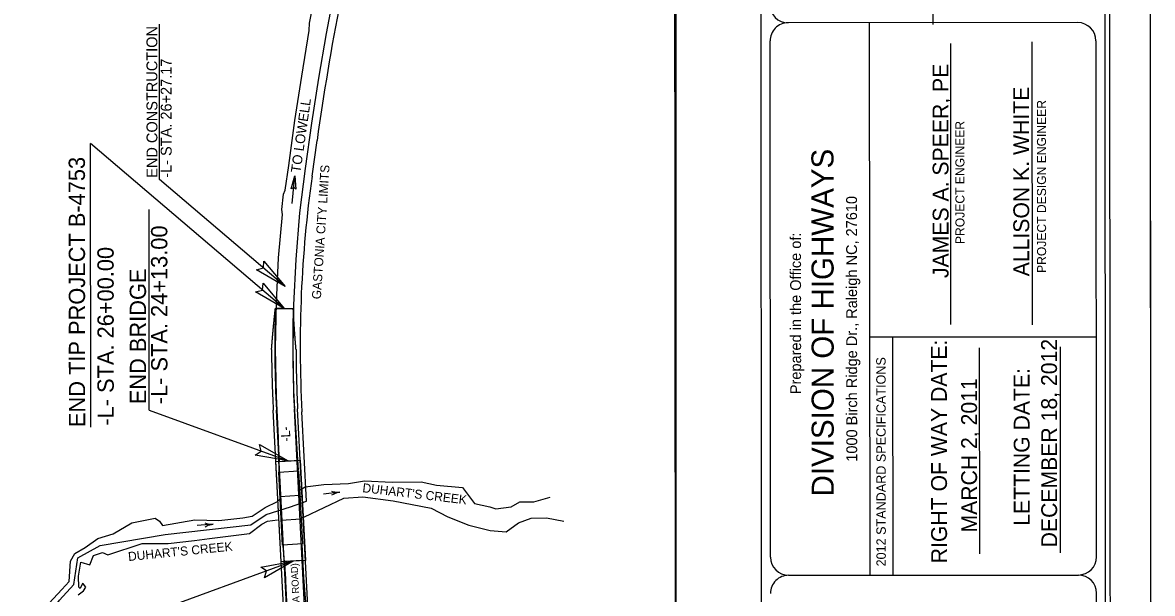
# Model space of a CAD drawing. Extents: x 1372027 to 1374286, y 553832 to 556743.
# Drawn here: x 1373560 to 1374184, y 554785 to 555100 of the extents above; entities that cross this region are included whole.
import ezdxf

# ---------------------------------------------------------------- set-up
doc = ezdxf.new("R2010")
doc.units = 0
for name, color, linetype in [('Default', 7, 'Continuous'), ('Prop Approach Slab', 7, 'Continuous'), ('Prop Approach Slab Hatching', 7, 'Continuous'), ('Prop Dimension', 7, 'Continuous'), ('Prop Dimension Text', 7, 'Continuous'), ('Prop EOT', 7, 'Continuous'), ('Prop Horizontal Alignment Curve and Spiral Data', 7, 'Continuous'), ('Prop Horizontal Alignment Station Label', 7, 'Continuous'), ('Prop North Arrow for Plan Sheets CELL', 7, 'Continuous'), ('Prop North Arrow NAD83 for Plan Sheets CELL', 7, 'Continuous'), ('Prop Paved Shoulder', 7, 'Continuous'), ('Prop Roadway Bridge', 7, 'Continuous'), ('Prop Shade Light', 7, 'Continuous'), ('Prop Structure Anchor Unit CELL', 7, 'Continuous'), ('Prop Terminator CELL', 7, 'Continuous'), ('Sheet Clip Boundary CELL', 7, 'Continuous'), ('Sheet Layout Plan Border', 7, 'Continuous'), ('Sheet Plan Layout CELL', 7, 'Continuous'), ('Sheet Plot Border Inside CELL', 7, 'Continuous')]:
    doc.layers.add(name, color=color, linetype=linetype)

msp = doc.modelspace()

# ---------------------------------------------------------------- linework, layer by layer
at = {"layer": 'Default'}
msp.add_line((1373708.71, 554999.98), (1373710.28, 555015.32), dxfattribs=at)
at = {"layer": 'Prop Approach Slab'}
msp.add_lwpolyline([(1374161.39, 553845.95), (1374159.91, 555512.45), (1373104.81, 555511.51), (1373106.29, 553845.01)], close=True, dxfattribs=at)
at = {"layer": 'Prop Approach Slab Hatching'}
msp.add_lwpolyline([(1373082.36, 555515.99), (1373083.86, 553831.99), (1374183.84, 553832.97), (1374182.35, 555516.97)], close=True, dxfattribs=at)
at = {"layer": 'Prop Dimension'}
for p, q in [((1373635.55, 555013.27), (1373635.48, 555099.03)), ((1373704.44, 554942), (1373597.42, 555033.13)), ((1373597.56, 554876.52), (1373597.42, 555033.13)), ((1373704.91, 554954.22), (1373635.55, 555013.27)), ((1373629.87, 554885.96), (1373629.77, 554996.81)), ((1373629.87, 554885.96), (1373706.54, 554857.91)), ((1373709.4, 554802.64), (1373629.97, 554773.41))]:
    msp.add_line(p, q, dxfattribs=at)
at = {"layer": 'Prop Dimension Text'}
for p, q in [((1373699.8, 554857.56), (1373713.28, 554858.26)), ((1373713.28, 554858.26), (1373716.14, 554802.98)), ((1373702.65, 554802.29), (1373699.8, 554857.56)), ((1373716.14, 554802.98), (1373702.65, 554802.29))]:
    msp.add_line(p, q, dxfattribs=at)
msp.add_lwpolyline([(1373448.16, 554513.79), (1373448.16, 555188.2), (1373920.65, 555188.2), (1373920.65, 554513.79)], close=True, dxfattribs=at)
at = {"layer": 'Prop EOT'}
for p, q in [((1373699.5, 554942.15), (1373709.39, 554941.86)), ((1373707.12, 554750.7), (1373700.13, 554886)), ((1373715.64, 554777.72), (1373710.02, 554886.51))]:
    msp.add_line(p, q, dxfattribs=at)
for radius in [695.7, 685.8]:
    msp.add_arc((1374394.9, 554921.9), radius, 178.33248, 182.95848, dxfattribs=at)
at = {"layer": 'Prop Horizontal Alignment Curve and Spiral Data'}
for p, q in [((1373702.12, 554838.27), (1373712.9, 554838.99)), ((1373713.51, 554825.81), (1373702.8, 554825.03))]:
    msp.add_line(p, q, dxfattribs=at)
msp.add_lwpolyline([(1373714.41, 554812.07), (1373703.39, 554811.4), (1373701.45, 554851.65), (1373712.34, 554852.38), (1373714.41, 554812.07)], dxfattribs=at)
at = {"layer": 'Prop North Arrow for Plan Sheets CELL'}
msp.add_lwpolyline([(1373708.29, 555008.2), (1373710.28, 555015.32), (1373710.82, 555007.9), (1373709.63, 555008.96)], close=True, dxfattribs=at)
at = {"layer": 'Prop Paved Shoulder'}
for p, q in [((1373706.49, 554728.14), (1373698.33, 554885.9)), ((1373717.94, 554768.14), (1373711.81, 554886.6))]:
    msp.add_line(p, q, dxfattribs=at)
for radius in [697.5, 684]:
    msp.add_arc((1374394.9, 554921.9), radius, 180.19879, 182.95848, dxfattribs=at)
for points in [[(1373697.41, 554919.48), (1373697.43, 554919.79), (1373697.45, 554920.1), (1373697.48, 554920.41), (1373697.5, 554920.71), (1373697.52, 554921.02), (1373697.55, 554921.33), (1373697.57, 554921.63), (1373697.6, 554921.94), (1373697.62, 554922.25), (1373697.65, 554922.55), (1373697.67, 554922.86), (1373697.7, 554923.17), (1373697.72, 554923.47), (1373697.75, 554923.78), (1373697.77, 554924.09), (1373697.8, 554924.39), (1373697.82, 554924.7), (1373697.85, 554925.01), (1373697.87, 554925.32), (1373697.9, 554925.62), (1373697.92, 554925.93), (1373697.95, 554926.24), (1373697.98, 554926.54), (1373698, 554926.85), (1373698.03, 554927.15), (1373698.06, 554927.46), (1373698.08, 554927.77), (1373698.11, 554928.07), (1373698.14, 554928.38), (1373698.16, 554928.69), (1373698.19, 554928.99), (1373698.22, 554929.3), (1373698.25, 554929.61), (1373698.28, 554929.91), (1373698.3, 554930.22), (1373698.33, 554930.53), (1373698.36, 554930.83), (1373698.39, 554931.14), (1373698.42, 554931.44), (1373698.44, 554931.75), (1373698.47, 554932.06), (1373698.5, 554932.36), (1373698.53, 554932.67), (1373698.56, 554932.98), (1373698.59, 554933.28), (1373698.62, 554933.59), (1373698.65, 554933.89), (1373698.68, 554934.2), (1373698.71, 554934.51), (1373698.74, 554934.81), (1373698.77, 554935.12), (1373698.8, 554935.42), (1373698.83, 554935.73), (1373698.86, 554936.04), (1373698.89, 554936.34), (1373698.92, 554936.65), (1373698.95, 554936.95), (1373698.98, 554937.26), (1373699.01, 554937.56), (1373699.04, 554937.87), (1373699.08, 554938.18), (1373699.11, 554938.48), (1373699.14, 554938.79), (1373699.17, 554939.09), (1373699.2, 554939.4), (1373699.24, 554939.7), (1373699.27, 554940.01), (1373699.3, 554940.32), (1373699.33, 554940.62), (1373699.36, 554940.93), (1373699.4, 554941.23), (1373699.43, 554941.54), (1373699.5, 554942.15)], [(1373710.91, 554919.53), (1373710.88, 554919.83), (1373710.86, 554920.13), (1373710.83, 554920.43), (1373710.81, 554920.73), (1373710.78, 554921.04), (1373710.76, 554921.34), (1373710.73, 554921.64), (1373710.71, 554921.94), (1373710.68, 554922.24), (1373710.66, 554922.54), (1373710.64, 554922.84), (1373710.61, 554923.14), (1373710.59, 554923.45), (1373710.56, 554923.75), (1373710.54, 554924.05), (1373710.52, 554924.35), (1373710.49, 554924.65), (1373710.47, 554924.95), (1373710.45, 554925.25), (1373710.43, 554925.56), (1373710.4, 554925.86), (1373710.38, 554926.16), (1373710.36, 554926.46), (1373710.34, 554926.76), (1373710.31, 554927.06), (1373710.29, 554927.36), (1373710.27, 554927.67), (1373710.25, 554927.97), (1373710.23, 554928.27), (1373710.2, 554928.57), (1373710.18, 554928.87), (1373710.16, 554929.17), (1373710.14, 554929.48), (1373710.12, 554929.78), (1373710.1, 554930.08), (1373710.08, 554930.38), (1373710.06, 554930.68), (1373710.04, 554930.98), (1373710.02, 554931.29), (1373710, 554931.59), (1373709.98, 554931.89), (1373709.96, 554932.19), (1373709.94, 554932.49), (1373709.92, 554932.8), (1373709.9, 554933.1), (1373709.88, 554933.4), (1373709.86, 554933.7), (1373709.84, 554934), (1373709.82, 554934.3), (1373709.8, 554934.61), (1373709.79, 554934.91), (1373709.77, 554935.21), (1373709.75, 554935.51), (1373709.73, 554935.81), (1373709.71, 554936.12), (1373709.69, 554936.42), (1373709.68, 554936.72), (1373709.66, 554937.02), (1373709.64, 554937.33), (1373709.62, 554937.63), (1373709.61, 554937.93), (1373709.59, 554938.23), (1373709.57, 554938.53), (1373709.55, 554938.84), (1373709.54, 554939.14), (1373709.52, 554939.44), (1373709.5, 554939.74), (1373709.49, 554940.05), (1373709.47, 554940.35), (1373709.46, 554940.65), (1373709.44, 554940.95), (1373709.42, 554941.26), (1373709.39, 554941.86)]]:
    msp.add_spline(points, degree=3, dxfattribs=at)
at = {"layer": 'Prop Roadway Bridge'}
for p, q in [((1373968.64, 554064.77), (1373967.37, 555484.77)), ((1374062.69, 555098.96), (1374062.5, 555319.63)), ((1374142.73, 555099.93), (1373982.73, 555099.79)), ((1374027.48, 555099.83), (1374027.74, 554794.83)), ((1373972.98, 554804.78), (1373972.73, 555089.78)), ((1374117.62, 554933.01), (1374117.48, 555089.26)), ((1374072.62, 554933.32), (1374072.49, 555088.47)), ((1374027.62, 554926.38), (1374152.87, 554926.49)), ((1374040.38, 554926.39), (1374040.49, 554794.84)), ((1374132.83, 554920.87), (1374132.93, 554807.12)), ((1374088.23, 554920.43), (1374088.33, 554806.68)), ((1374040.4, 554888.49), (1374040.4, 554888.49)), ((1374088.29, 554863.53), (1374088.29, 554863.53)), ((1373982.99, 554794.79), (1374142.99, 554794.93))]:
    msp.add_line(p, q, dxfattribs=at)
for points in [[(1374158.7, 554009.94), (1374157.38, 555489.94)], [(1374152.98, 554804.94), (1374152.74, 555089.94)], [(1374153.35, 554404.94), (1374153.01, 554784.94)]]:
    msp.add_lwpolyline(points, dxfattribs=at)
for centre, start, end in [((1373982.66, 555109.79), 180.05095, 270.05095), ((1373982.68, 555089.79), 90.05095, 180.05095), ((1374142.68, 555089.93), 0.05095, 90.05095), ((1373982.93, 554804.79), 180.05095, 270.05095), ((1374142.93, 554804.93), 270.05095, 0.05095), ((1373982.95, 554784.79), 90.05095, 180.05095), ((1374142.95, 554784.93), 0.05095, 90.05095)]:
    msp.add_arc(centre, 10, start, end, dxfattribs=at)
at = {"layer": 'Prop Shade Light'}
msp.add_line((1373700.13, 554886), (1373701.59, 554857.66), dxfattribs=at)
for points in [[(1373709.39, 554941.86), (1373704.44, 554942), (1373699.5, 554942.15)], [(1373701.59, 554857.66), (1373711.48, 554858.17), (1373710.02, 554886.51)]]:
    msp.add_lwpolyline(points, dxfattribs=at)
msp.add_lwpolyline([(1373714.34, 554802.89), (1373704.46, 554802.38), (1373707.12, 554750.7), (1373709.42, 554705.76), (1373714.39, 554706.01), (1373719.33, 554706.27), (1373717.01, 554751.21)], close=True, dxfattribs=at)
for radius in [695.7, 685.8]:
    msp.add_arc((1374394.9, 554921.9), radius, 178.33248, 182.95848, dxfattribs=at)
at = {"layer": 'Prop Structure Anchor Unit CELL'}
msp.add_line((1374183.84, 553832.97), (1374182.35, 555516.97), dxfattribs=at)
at = {"layer": 'Prop Terminator CELL'}
for points in [[(1373719.76, 555015.1), (1373722.54, 555034.92)], [(1373716.77, 554835.64), (1373714.15, 554885.05)], [(1373508.72, 554630.78), (1373513.73, 554667.88), (1373511.28, 554712.53), (1373529.75, 554755.21), (1373574.28, 554772.47), (1373580.36, 554781.04), (1373588.29, 554789.72), (1373590.48, 554804.48), (1373602.72, 554811.26), (1373638.71, 554817.3), (1373685.99, 554822.67), (1373694.48, 554828.39), (1373707.82, 554832.57), (1373716.77, 554835.64)]]:
    msp.add_lwpolyline(points, dxfattribs=at)
for points in [[(1373693.21, 554968.25), (1373704.91, 554954.22), (1373689.05, 554963.52), (1373692.88, 554964.46)], [(1373692.75, 554956.03), (1373704.44, 554942), (1373688.59, 554951.3), (1373692.41, 554952.25)], [(1373690.7, 554867.01), (1373706.54, 554857.91), (1373688.44, 554861.13), (1373691.7, 554863.34)], [(1373691.44, 554799.33), (1373709.4, 554802.64), (1373693.52, 554793.38), (1373694.57, 554797.18)]]:
    msp.add_lwpolyline(points, close=True, dxfattribs=at)
for centre, radius, start, end in [((1375172.7, 554831.81), 1464.32, 165.9137, 172.027), ((1374391.75, 554920.98), 678.55, 172.027, 183.03553)]:
    msp.add_arc(centre, radius, start, end, dxfattribs=at)
at = {"layer": 'Sheet Clip Boundary CELL'}
msp.add_lwpolyline([(1373920.63, 554536.72), (1373920.07, 555166.73), (1373542.74, 555166.39), (1373542.82, 555081.22), (1373447.65, 555081.14), (1373448.5, 554711.84), (1373547.67, 554711.94), (1373547.83, 554537.32)], close=True, dxfattribs=at)
at = {"layer": 'Sheet Layout Plan Border'}
for p, q in [((1373739.98, 554845.53), (1373748.79, 554846.93)), ((1373748.79, 554846.93), (1373763.99, 554846.27)), ((1373763.99, 554846.27), (1373780.03, 554846.41)), ((1373780.03, 554846.41), (1373788.56, 554844.47)), ((1373713.73, 554842.37), (1373716.04, 554843.59)), ((1373714.24, 554839.67), (1373713.73, 554842.37)), ((1373714.28, 554838.3), (1373714.24, 554839.67)), ((1373716.04, 554843.59), (1373726.29, 554844.84)), ((1373735.08, 554840.76), (1373726.17, 554839.56)), ((1373726.29, 554844.84), (1373739.98, 554845.53)), ((1373730.49, 554841.18), (1373731.38, 554840.94)), ((1373730.62, 554840.16), (1373730.62, 554840.16)), ((1373730.76, 554839.14), (1373731.56, 554839.61)), ((1373731.38, 554840.94), (1373732.29, 554840.78)), ((1373731.56, 554839.61), (1373732.4, 554840.01)), ((1373732.29, 554840.78), (1373733.23, 554840.69)), ((1373732.4, 554840.01), (1373733.28, 554840.34)), ((1373733.23, 554840.69), (1373734.17, 554840.67)), ((1373733.28, 554840.34), (1373734.17, 554840.61)), ((1373734.17, 554840.61), (1373735.08, 554840.76)), ((1373734.17, 554840.67), (1373735.08, 554840.76)), ((1373788.56, 554844.47), (1373802.94, 554843.26)), ((1373802.94, 554843.26), (1373809.51, 554834.44)), ((1373693.85, 554832.13), (1373700.73, 554835.46)), ((1373700.73, 554835.46), (1373702.16, 554836.99)), ((1373713.06, 554838.23), (1373714.28, 554838.3)), ((1373715.58, 554827.07), (1373737.26, 554837.38)), ((1373737.26, 554837.38), (1373747.82, 554838.08)), ((1373747.82, 554838.08), (1373764.49, 554835.82)), ((1373764.49, 554835.82), (1373785.51, 554831.85)), ((1373809.51, 554834.44), (1373817.99, 554832.65)), ((1373829.81, 554832.59), (1373834.42, 554835.3)), ((1373834.42, 554835.3), (1373842.23, 554835.35)), ((1373842.23, 554835.35), (1373851.29, 554837.85)), ((1373681.49, 554826.56), (1373686.69, 554827.5)), ((1373686.69, 554827.5), (1373693.85, 554832.13)), ((1373713.66, 554826.7), (1373715.58, 554827.07)), ((1373785.51, 554831.85), (1373794.7, 554826.99)), ((1373794.7, 554826.99), (1373806.43, 554822.44)), ((1373817.99, 554832.65), (1373821.3, 554831.44)), ((1373821.3, 554831.44), (1373829.81, 554832.59)), ((1373609.97, 554817.61), (1373620.3, 554823.73)), ((1373620.3, 554823.73), (1373633.1, 554826.23)), ((1373633.1, 554826.23), (1373635.59, 554824.69)), ((1373635.59, 554824.69), (1373637.18, 554822.21)), ((1373637.18, 554822.21), (1373655.12, 554825.32)), ((1373655.12, 554825.32), (1373668.33, 554825.08)), ((1373665.21, 554822.99), (1373656.23, 554822.31)), ((1373660.64, 554823.67), (1373661.52, 554823.39)), ((1373660.72, 554822.65), (1373660.72, 554822.65)), ((1373660.8, 554821.62), (1373661.62, 554822.04)), ((1373661.52, 554823.39), (1373662.42, 554823.17)), ((1373661.62, 554822.04), (1373662.48, 554822.39)), ((1373662.42, 554823.17), (1373663.35, 554823.02)), ((1373662.48, 554822.39), (1373663.38, 554822.68)), ((1373663.35, 554823.02), (1373664.28, 554822.95)), ((1373663.38, 554822.68), (1373664.29, 554822.89)), ((1373664.28, 554822.95), (1373665.21, 554822.99)), ((1373664.29, 554822.89), (1373665.21, 554822.99)), ((1373668.33, 554825.08), (1373681.49, 554826.56)), ((1373685.29, 554817.84), (1373692.07, 554823)), ((1373692.07, 554823), (1373695.11, 554824.64)), ((1373695.11, 554824.64), (1373700.74, 554825.48)), ((1373806.43, 554822.44), (1373818.04, 554819.6)), ((1373827.02, 554818.82), (1373833.82, 554823.82)), ((1373833.82, 554823.82), (1373840.78, 554826.37)), ((1373840.78, 554826.37), (1373849.23, 554826.42)), ((1373849.23, 554826.42), (1373858.72, 554824.73)), ((1373594.48, 554810.17), (1373601.42, 554815.17)), ((1373601.42, 554815.17), (1373609.97, 554817.61)), ((1373654.88, 554814.02), (1373663.15, 554815.09)), ((1373663.15, 554815.09), (1373685.29, 554817.84)), ((1373818.04, 554819.6), (1373827.02, 554818.82)), ((1373588.85, 554806.86), (1373594.48, 554810.17)), ((1373606.97, 554806.12), (1373626.01, 554812.24)), ((1373626.01, 554812.24), (1373640.24, 554812.38)), ((1373640.24, 554812.38), (1373654.88, 554814.02)), ((1373585.65, 554791.26), (1373586.43, 554802.66)), ((1373585.65, 554791.26), (1373586.43, 554802.66)), ((1373586.43, 554802.66), (1373588.85, 554806.86)), ((1373590.71, 554794.28), (1373592.11, 554802.11)), ((1373592.11, 554802.11), (1373597.03, 554800.56)), ((1373597.03, 554800.56), (1373599, 554805.62)), ((1373599, 554805.62), (1373604.03, 554807.34)), ((1373604.03, 554807.34), (1373606.97, 554806.12)), ((1373581.62, 554786.93), (1373585.65, 554791.26)), ((1373590.93, 554788.18), (1373590.71, 554794.28)), ((1373592.97, 554790.31), (1373591.65, 554787.47)), ((1373593.47, 554789.87), (1373592.97, 554790.31)), ((1373594.77, 554788.28), (1373593.47, 554789.87)), ((1373574.57, 554779.47), (1373581.62, 554786.93)), ((1373590.52, 554783.99), (1373593.55, 554786.13)), ((1373591.65, 554787.47), (1373590.93, 554788.18)), ((1373593.55, 554786.13), (1373594.77, 554788.28))]:
    msp.add_line(p, q, dxfattribs=at)
at = {"layer": 'Sheet Plot Border Inside CELL'}
for points in [[(1373701.61, 554851.79), (1373701.21, 554870.75), (1373700.2, 554893.75), (1373699.62, 554920.02), (1373700.18, 554945.38), (1373701.21, 554970.07), (1373703.46, 554994.03), (1373703.11, 554996.83), (1373704.03, 555005.17), (1373704.94, 555007.48), (1373706.87, 555021.03), (1373710.29, 555045.83), (1373714.09, 555070.37), (1373718.12, 555095.57), (1373718.29, 555099.56), (1373719.79, 555107.01), (1373720.66, 555109.37), (1373721.37, 555111.69), (1373722.93, 555119.85), (1373727.71, 555143.54), (1373732.97, 555167.75)], [(1373743.23, 555168.72), (1373742.35, 555165.46), (1373736.85, 555141.77), (1373732.18, 555118.17), (1373727.58, 555093.88), (1373723.31, 555069.18), (1373719.46, 555044.41), (1373715.92, 555019.44), (1373712.89, 554994.91), (1373710.72, 554969.19), (1373709.46, 554944.12), (1373709.13, 554919.48), (1373709.47, 554894.39), (1373710.94, 554870.53), (1373712.05, 554852.76)], [(1373717.7, 554605.01), (1373714.78, 554626.79), (1373714.14, 554627.48), (1373713.11, 554637.3), (1373713.51, 554638.48), (1373712.94, 554647.49), (1373711.47, 554670.47), (1373710.73, 554682.74), (1373710.3, 554684.1), (1373710.09, 554688.16), (1373710.1, 554690.71), (1373709.24, 554711.76), (1373708.05, 554731.98), (1373706.91, 554749.71), (1373706.47, 554752.2), (1373705.97, 554762.63), (1373705.75, 554772.65), (1373705.23, 554792.94), (1373703.75, 554811.22)], [(1373714.21, 554811.82), (1373715.02, 554793.47), (1373716.37, 554777.76), (1373716.17, 554772.76), (1373717.82, 554759.68), (1373718.3, 554749.77), (1373717.85, 554741.51), (1373718.04, 554732.79), (1373719.39, 554712.27), (1373720.56, 554690.69), (1373721.68, 554669.89), (1373722.84, 554647.98), (1373724.62, 554627.55), (1373727.82, 554606.64), (1373733.37, 554583.58), (1373739.54, 554562.71), (1373746.42, 554542.5), (1373749.23, 554534.64)]]:
    msp.add_lwpolyline(points, dxfattribs=at)

# ---------------------------------------------------------------- texts
at = {"layer": 'Default'}
for s, height, rotation, p in [('TO LOWELL', 5.4, 81.88633, (1373713.36, 555016.77)), ('GASTONIA CITY LIMITS', 4.95, 86.22803, (1373724.59, 554947.08)), ("DUHART'S CREEK", 4.95, 353.29214, (1373747.4, 554840.71)), ("DUHART'S CREEK", 4.95, 5.74488, (1373618.43, 554802.63)), ('SR 2439 (LOWELL BETHESDA ROAD)', 3.888, 92.999, (1373716.6, 554709.49))]:
    msp.add_text(s, height=height, rotation=rotation, dxfattribs=at).set_placement(p)
at = {"layer": 'Prop Horizontal Alignment Station Label'}
msp.add_text('-L-', height=5.118, rotation=92.97626, dxfattribs=at).set_placement((1373707.9, 554868.74))
at = {"layer": 'Prop North Arrow NAD83 for Plan Sheets CELL'}
for s, p in [('JAMES A. SPEER, PE', (1374071.3, 554958.89)), ('ALLISON K. WHITE', (1374115.83, 554959.85)), ('DECEMBER 18, 2012', (1374131.24, 554810.19)), ('MARCH 2, 2011 ', (1374087.04, 554818.38))]:
    msp.add_text(s, height=8.7501, rotation=90.05095, dxfattribs=at).set_placement(p)
at = {"layer": 'Prop Roadway Bridge'}
for s, height, p in [('PROJECT DESIGN ENGINEER', 4.9995, (1374125.15, 554961.71)), ('PROJECT ENGINEER', 4.9995, (1374080.08, 554977.67)), ('DIVISION OF HIGHWAYS', 12.1872, (1374007.9, 554838.3)), ('1000 Birch Ridge Dr., Raleigh NC, 27610', 6, (1374020.83, 554857.48)), ('Prepared in the Office of:', 5.9994, (1373989.86, 554894.79)), ('RIGHT OF WAY DATE: ', 8.7498, (1374070.43, 554801.42)), ('2012 STANDARD SPECIFICATIONS', 5.2, (1374036.63, 554799.68)), ('LETTING DATE:', 8.7498, (1374116.06, 554822.11))]:
    msp.add_text(s, height=height, rotation=90.05095, dxfattribs=at).set_placement(p)
at = {"layer": 'Sheet Plan Layout CELL'}
for s, height, p in [('END CONSTRUCTION', 6, (1373634.38, 555014.25)), ('-L- STA. 26+27.17', 6, (1373642.24, 555014.26)), ('END TIP PROJECT B-4753', 9, (1373594.48, 554876.65)), ('-L- STA. 24+13.00', 9, (1373639.92, 554889.25)), ('-L- STA. 26+00.00 ', 9, (1373610.29, 554877.41)), ('END BRIDGE', 9, (1373628.12, 554889.24))]:
    msp.add_text(s, height=height, rotation=90.05095, dxfattribs=at).set_placement(p)

doc.saveas('drawing.dxf')
